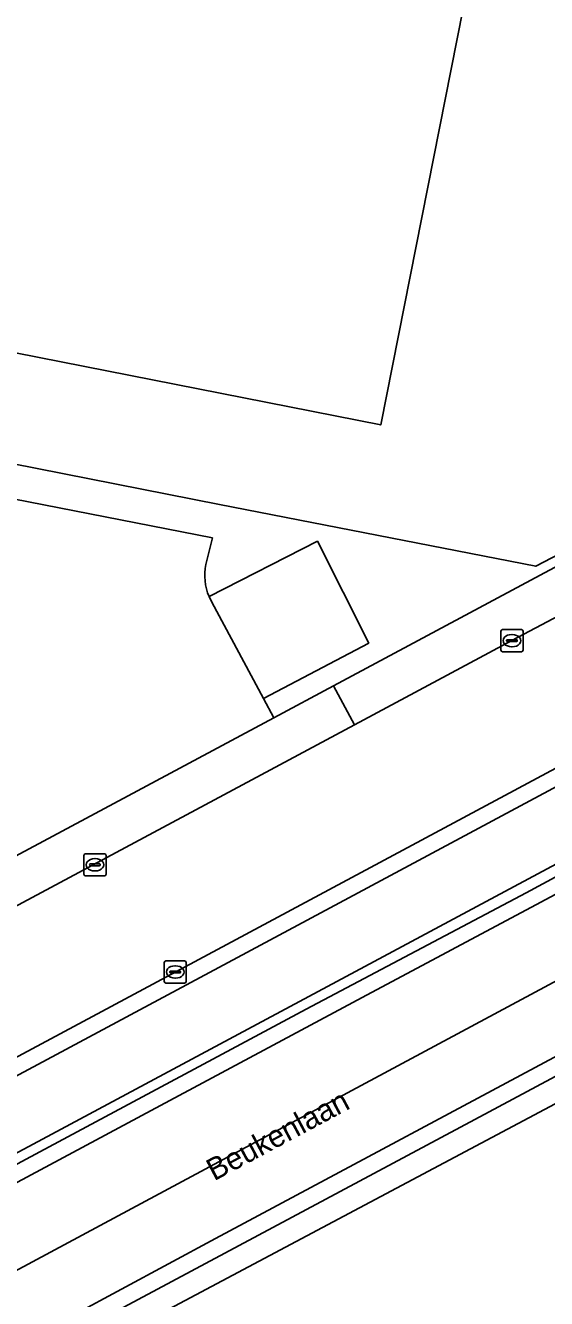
# Model space of a CAD drawing. Extents: x 158793 to 159888, y 384317 to 385256.
# Drawn here: x 159641.5 to 159665.2, y 384405.5 to 384463.1 of the extents above; entities that cross this region are included whole.
import ezdxf

# ---------------------------------------------------------------- set-up
doc = ezdxf.new("R2010")
doc.units = 0
for name, color, linetype in [('IMGEO_Berm_gesloten', 7, 'Continuous'), ('IMGEO_Berm_open', 7, 'Continuous'), ('IMGEO_Erf', 7, 'Continuous'), ('IMGEO_Fietspad_gesloten', 7, 'Continuous'), ('IMGEO_Kolk', 7, 'Continuous'), ('IMGEO_Openbare_ruimte_label', 7, 'Continuous'), ('IMGEO_Pand', 7, 'Continuous'), ('IMGEO_Parkeervlak_open', 7, 'Continuous'), ('IMGEO_Rijbaan_lokaal_gesloten', 7, 'Continuous'), ('IMGEO_Rijbaan_regionaal_gesloten', 7, 'Continuous'), ('IMGEO_Verkeerseiland_open', 7, 'Continuous'), ('IMGEO_Voetpad_open', 7, 'Continuous')]:
    doc.layers.add(name, color=color, linetype=linetype)

msp = doc.modelspace()

# ---------------------------------------------------------------- linework, layer by layer
at = {"layer": 'IMGEO_Berm_gesloten'}
msp.add_lwpolyline([(159667.67, 384417.548), (159650.153, 384408.169), (159630.958, 384397.851), (159616.488, 384390.102), (159616.87, 384389.389), (159631.206, 384397.094), (159644.473, 384404.254), (159661.921, 384413.563), (159679.569, 384423.013)], dxfattribs=at)
at = {"layer": 'IMGEO_Berm_open'}
for points in [[(159642.609, 384412.337), (159654.268, 384418.57), (159664.238, 384423.844), (159672.561, 384428.328), (159683.971, 384434.448), (159692.958, 384439.23), (159693.288, 384438.625), (159701.548, 384443.077), (159705.803, 384445.325), (159705.22, 384446.356), (159692.734, 384439.673), (159612.839, 384396.912), (159613.053, 384396.512), (159617.171, 384398.703), (159622.895, 384401.766), (159624.993, 384402.897)], [(159656.81, 384419.099), (159673.007, 384427.734), (159687.108, 384435.294), (159693.288, 384438.625), (159692.958, 384439.23), (159683.971, 384434.448), (159672.561, 384428.328), (159664.238, 384423.844), (159654.268, 384418.57), (159642.609, 384412.337), (159624.993, 384402.897), (159622.895, 384401.766), (159617.171, 384398.703), (159613.053, 384396.512), (159613.401, 384395.863), (159613.635, 384395.988), (159617.694, 384398.165), (159626.551, 384402.935), (159637.604, 384408.821), (159647.237, 384413.981)]]:
    msp.add_lwpolyline(points, close=True, dxfattribs=at)
at = {"layer": 'IMGEO_Erf'}
msp.add_lwpolyline([(159665.104, 384482.719), (159657.652, 384445.044), (159634.856, 384449.536), (159634.884, 384450.102), (159624.284, 384452.245), (159624.125, 384451.684), (159608.374, 384454.809), (159607.652, 384454.952), (159606.689, 384450.048), (159650.339, 384441.442), (159664.679, 384438.637), (159682.172, 384447.751)], dxfattribs=at)
at = {"layer": 'IMGEO_Fietspad_gesloten'}
for points in [[(159707.394, 384451.026), (159691.341, 384442.43), (159554.532, 384369.175), (159553.562, 384368.656), (159553.639, 384368.525), (159551.212, 384367.259)], [(159548.945, 384362.714), (159562.5, 384369.97), (159562.977, 384370.225), (159610.25, 384395.526), (159612.839, 384396.912), (159692.734, 384439.673)]]:
    msp.add_lwpolyline(points, dxfattribs=at)
at = {"layer": 'IMGEO_Kolk'}
for p, q in [((159663.101, 384434.84), (159663.101, 384435.692)), ((159663.176, 384435.766), (159664.028, 384435.766)), ((159663.36, 384435.26), (159663.36, 384435.272)), ((159663.403, 384435.309), (159663.801, 384435.309)), ((159663.589, 384435.546), (159663.614, 384435.546)), ((159663.844, 384435.272), (159663.844, 384435.26)), ((159664.102, 384435.692), (159664.102, 384434.84)), ((159664.028, 384434.766), (159663.176, 384434.766)), ((159663.798, 384435.223), (159663.4, 384435.223)), ((159663.612, 384434.986), (159663.587, 384434.986)), ((159644.191, 384424.683), (159644.191, 384425.535)), ((159644.266, 384425.609), (159645.118, 384425.609)), ((159645.192, 384425.535), (159645.192, 384424.683)), ((159644.45, 384425.103), (159644.45, 384425.115)), ((159644.888, 384425.066), (159644.49, 384425.066)), ((159644.493, 384425.152), (159644.891, 384425.152)), ((159644.679, 384425.389), (159644.704, 384425.389)), ((159644.934, 384425.115), (159644.934, 384425.103)), ((159645.118, 384424.609), (159644.266, 384424.609)), ((159644.702, 384424.829), (159644.677, 384424.829)), ((159647.831, 384419.827), (159647.831, 384420.679)), ((159647.906, 384420.753), (159648.758, 384420.753)), ((159648.09, 384420.247), (159648.09, 384420.259)), ((159648.133, 384420.296), (159648.531, 384420.296)), ((159648.319, 384420.533), (159648.344, 384420.533)), ((159648.574, 384420.259), (159648.574, 384420.247)), ((159648.832, 384420.679), (159648.832, 384419.827)), ((159648.758, 384419.753), (159647.906, 384419.753)), ((159648.528, 384420.21), (159648.13, 384420.21)), ((159648.342, 384419.973), (159648.317, 384419.973))]:
    msp.add_line(p, q, dxfattribs=at)
for points in [[(159663.101, 384434.84), (159663.101, 384435.692)], [(159663.176, 384435.766), (159664.028, 384435.766)], [(159664.102, 384435.692), (159664.102, 384434.84)], [(159664.028, 384434.766), (159663.176, 384434.766)], [(159644.191, 384424.683), (159644.191, 384425.535)], [(159644.266, 384425.609), (159645.118, 384425.609)], [(159645.192, 384425.535), (159645.192, 384424.683)], [(159645.118, 384424.609), (159644.266, 384424.609)], [(159647.831, 384419.827), (159647.831, 384420.679)], [(159647.906, 384420.753), (159648.758, 384420.753)], [(159648.832, 384420.679), (159648.832, 384419.827)], [(159648.758, 384419.753), (159647.906, 384419.753)]]:
    msp.add_lwpolyline(points, dxfattribs=at)
for centre, radius, start, end in [((159663.178, 384435.69), 0.0765, 91.55205, 178.44795), ((159663.178, 384435.69), 0.0765, 91.55205, 178.44795), ((159663.4, 384435.269), 0.0403, 85.87752, 175.75265), ((159663.397, 384435.259), 0.0366, 178.93798, 274.71019), ((159663.801, 384435.266), 0.043, 264.86636, 352.45326), ((159663.805, 384435.271), 0.0386, 1.73085, 96.63898), ((159664.026, 384435.69), 0.0765, 1.55205, 88.44795), ((159664.026, 384435.69), 0.0765, 1.55205, 88.44795), ((159663.178, 384434.842), 0.0765, 181.55205, 268.44795), ((159663.178, 384434.842), 0.0765, 181.55205, 268.44795), ((159664.026, 384434.842), 0.0765, 271.55205, 358.44795), ((159664.026, 384434.842), 0.0765, 271.55205, 358.44795), ((159644.268, 384425.533), 0.0765, 91.55205, 178.44795), ((159644.268, 384425.533), 0.0765, 91.55205, 178.44795), ((159645.116, 384425.533), 0.0765, 1.55205, 88.44795), ((159645.116, 384425.533), 0.0765, 1.55205, 88.44795), ((159644.49, 384425.112), 0.0403, 85.87752, 175.75265), ((159644.487, 384425.102), 0.0366, 178.93798, 274.71019), ((159644.891, 384425.109), 0.043, 264.86636, 352.45326), ((159644.895, 384425.114), 0.0386, 1.73085, 96.63898), ((159644.268, 384424.685), 0.0765, 181.55205, 268.44795), ((159644.268, 384424.685), 0.0765, 181.55205, 268.44795), ((159645.116, 384424.685), 0.0765, 271.55205, 358.44795), ((159645.116, 384424.685), 0.0765, 271.55205, 358.44795), ((159647.908, 384420.677), 0.0765, 91.55205, 178.44795), ((159647.908, 384420.677), 0.0765, 91.55205, 178.44795), ((159648.13, 384420.256), 0.0403, 85.87752, 175.75265), ((159648.535, 384420.258), 0.0386, 1.73085, 96.63898), ((159648.756, 384420.677), 0.0765, 1.55205, 88.44795), ((159648.756, 384420.677), 0.0765, 1.55205, 88.44795), ((159647.908, 384419.829), 0.0765, 181.55205, 268.44795), ((159647.908, 384419.829), 0.0765, 181.55205, 268.44795), ((159648.127, 384420.246), 0.0366, 178.93798, 274.71019), ((159648.531, 384420.253), 0.043, 264.86636, 352.45326), ((159648.756, 384419.829), 0.0765, 271.55205, 358.44795), ((159648.756, 384419.829), 0.0765, 271.55205, 358.44795)]:
    msp.add_arc(centre, radius, start, end, dxfattribs=at)
for centre, major_axis, ratio, start_param, end_param in [((159663.588, 384435.266), (-0.387, 0.002), 0.722429, 4.712389, 7.853982), ((159663.613, 384435.266), (-0.39, 0.002), 0.717154, 1.570796, 4.712389), ((159644.678, 384425.109), (-0.387, 0.002), 0.722429, 4.712389, 7.853982), ((159644.703, 384425.109), (-0.39, 0.002), 0.717154, 1.570796, 4.712389), ((159648.318, 384420.253), (-0.387, 0.002), 0.722429, 4.712389, 7.853982), ((159648.343, 384420.253), (-0.39, 0.002), 0.717154, 1.570796, 4.712389)]:
    msp.add_ellipse(centre, major_axis=major_axis, ratio=ratio, start_param=start_param, end_param=end_param, dxfattribs=at)
at = {"layer": 'IMGEO_Pand'}
msp.add_lwpolyline([(159608.374, 384454.809), (159624.125, 384451.684), (159624.284, 384452.245), (159634.884, 384450.102), (159634.856, 384449.536), (159657.652, 384445.044), (159665.104, 384482.719), (159663.062, 384483.15), (159663.172, 384483.741), (159642.371, 384487.828), (159642.299, 384487.34), (159631.594, 384489.43), (159631.646, 384489.94), (159615.168, 384493.218), (159607.652, 384454.952)], close=True, dxfattribs=at)
at = {"layer": 'IMGEO_Parkeervlak_open'}
msp.add_lwpolyline([(159649.866, 384437.26), (159649.99, 384437.008), (159652.339, 384432.641), (159657.107, 384435.157), (159654.782, 384439.768)], close=True, dxfattribs=at)
at = {"layer": 'IMGEO_Rijbaan_lokaal_gesloten'}
msp.add_lwpolyline([(159691, 384443.105), (159706.671, 384451.498), (159703.8, 384456.78), (159699.775, 384454.613), (159693.473, 384451.244), (159688.29, 384448.468), (159683.468, 384445.886), (159667.341, 384437.251), (159663.602, 384435.266), (159656.463, 384431.445), (159640.576, 384422.941), (159639.863, 384422.559), (159627.52, 384415.953), (159609.483, 384406.293), (159608.385, 384405.705), (159578.043, 384389.447), (159576.947, 384388.86), (159572.485, 384386.47), (159563.362, 384381.583), (159561.547, 384380.611), (159552.342, 384375.685), (159550.262, 384374.58), (159553.184, 384369.293)], close=True, dxfattribs=at)
for points in [[(159649.715, 384438.714), (159650.018, 384439.921), (159607.516, 384448.232)], [(159605.487, 384414.336), (159615.678, 384419.713), (159628.056, 384426.244), (159637.645, 384431.379), (159640.014, 384426.956), (159640.503, 384426.042), (159640.859, 384425.377), (159652.805, 384431.774), (159652.339, 384432.641), (159649.99, 384437.008), (159649.866, 384437.26)]]:
    msp.add_lwpolyline(points, dxfattribs=at)
msp.add_arc((159652.187, 384438.236), 2.518, 169.05592, 202.80207, dxfattribs=at)
at = {"layer": 'IMGEO_Rijbaan_regionaal_gesloten'}
msp.add_lwpolyline([(159617.271, 384388.641), (159617.372, 384388.695), (159756.881, 384462.779), (159884.047, 384528.944), (159883.694, 384529.35), (159881.307, 384528.22), (159875.887, 384525.604), (159825.453, 384500), (159812.356, 384493.351), (159791.799, 384482.795), (159777.564, 384475.395), (159744.535, 384457.751), (159731.675, 384450.855), (159717.186, 384443.101), (159697.88, 384432.802), (159696.562, 384432.097), (159679.569, 384423.013), (159661.921, 384413.563), (159644.473, 384404.254), (159631.206, 384397.094), (159616.87, 384389.389)], close=True, dxfattribs=at)
for points in [[(159673.007, 384427.734), (159656.81, 384419.099), (159647.237, 384413.981), (159637.604, 384408.821), (159626.551, 384402.935), (159617.694, 384398.165), (159613.635, 384395.988), (159613.401, 384395.863), (159615.068, 384392.753), (159645.738, 384409.21), (159694.585, 384435.384)], [(159694.585, 384435.384), (159645.738, 384409.21), (159615.068, 384392.753), (159616.488, 384390.102), (159630.958, 384397.851), (159650.153, 384408.169), (159667.67, 384417.548)]]:
    msp.add_lwpolyline(points, dxfattribs=at)
at = {"layer": 'IMGEO_Verkeerseiland_open'}
msp.add_lwpolyline([(159708.918, 384452.702), (159706.671, 384451.498), (159691, 384443.105), (159553.184, 384369.293), (159553.562, 384368.656), (159554.532, 384369.175), (159691.341, 384442.43)], dxfattribs=at)
at = {"layer": 'IMGEO_Voetpad_open'}
for points in [[(159682.984, 384450.639), (159680.012, 384456.195), (159679.597, 384455.98), (159682.698, 384450.091), (159682.172, 384447.751), (159664.679, 384438.637), (159650.339, 384441.442), (159606.689, 384450.048), (159607.652, 384454.952), (159615.168, 384493.218), (159617.255, 384503.352), (159616.365, 384503.523), (159616.635, 384504.924), (159619.025, 384517.345)], [(159606.273, 384448.548), (159607.516, 384448.232), (159650.018, 384439.921), (159649.715, 384438.714)], [(159649.866, 384437.26), (159654.782, 384439.768), (159657.107, 384435.157), (159652.339, 384432.641), (159652.805, 384431.774), (159655.504, 384433.219), (159666.374, 384439.04), (159683.461, 384448.173)], [(159666.374, 384439.04), (159655.504, 384433.219), (159656.463, 384431.445), (159663.602, 384435.266), (159667.341, 384437.251)]]:
    msp.add_lwpolyline(points, dxfattribs=at)
msp.add_lwpolyline([(159656.463, 384431.445), (159655.504, 384433.219), (159652.805, 384431.774), (159640.859, 384425.377), (159639.63, 384424.719), (159640.576, 384422.941)], close=True, dxfattribs=at)
msp.add_arc((159652.187, 384438.236), 2.518, 169.05592, 202.80207, dxfattribs=at)

# ---------------------------------------------------------------- texts
at = {"layer": 'IMGEO_Openbare_ruimte_label'}
msp.add_text('Beukenlaan', height=1, rotation=28.10282, dxfattribs=at).set_placement((159650.095, 384410.764))

doc.saveas('drawing.dxf')
